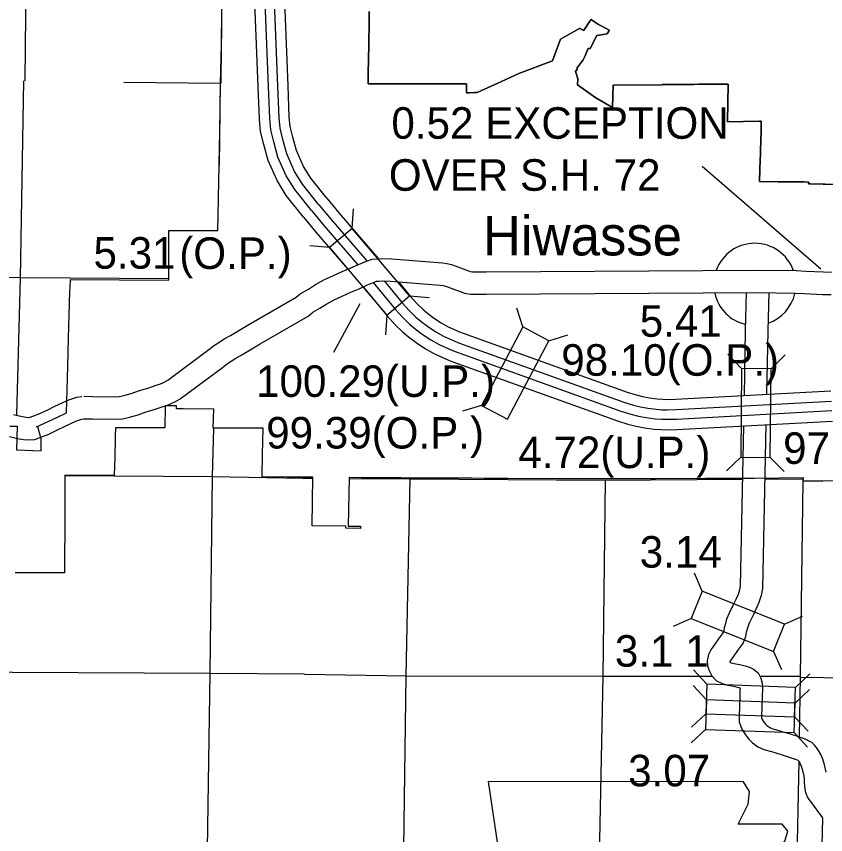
# Model space of a CAD drawing. Extents: x 77230 to 630905, y 790554 to 1662844.
# Drawn here: x 176223 to 197917, y 1598656 to 1620575 of the extents above; entities that cross this region are included whole.
import ezdxf

# ---------------------------------------------------------------- set-up
doc = ezdxf.new("R2010")
doc.units = 0
for name, color, linetype in [('Level 12', 7, 'Continuous'), ('Level 15', 7, 'Continuous'), ('Level 16', 7, 'Continuous'), ('Level 19', 7, 'Continuous'), ('Level 22', 7, 'Continuous'), ('Level 24', 7, 'Continuous'), ('Level 26', 7, 'Continuous'), ('Level 27', 7, 'Continuous'), ('Level 29', 7, 'Continuous'), ('Level 31', 7, 'Continuous'), ('Level 32', 7, 'Continuous')]:
    doc.layers.add(name, color=color, linetype=linetype)

msp = doc.modelspace()

# ---------------------------------------------------------------- linework, layer by layer
at = {"layer": 'Level 12'}
for points in [[(176051, 1609595), (176241, 1609593), (176225, 1608965), (176884, 1608940), (176891, 1609260), (176802, 1609576), (176767, 1609577), (177307, 1609829), (177570, 1609952), (177586, 1610561), (177595, 1610905), (177602, 1611196), (177622, 1611963), (177630, 1612245), (177630, 1612263), (177661, 1613207), (177664, 1613308), (177671, 1613525), (178990, 1613514), (180307, 1613505), (180311, 1614841), (181620, 1614836), (181629, 1615240), (181649, 1616163), (181678, 1617493), (181697, 1618767), (181731, 1620161), (181735, 1621439)], [(191270, 1618905), (191211, 1619095), (191257, 1619158), (191252, 1619195), (191417, 1619408), (191451, 1619486), (191549, 1619713), (191568, 1619715), (191568, 1619715), (191601, 1619718), (191780, 1620065), (192060, 1620110), (192112, 1620200), (192114, 1620203), (191938, 1620300), (191868, 1620338), (191828, 1620361), (191775, 1620394), (191719, 1620431), (191671, 1620466), (191637, 1620491), (191636, 1620492), (191539, 1620362), (191494, 1620296), (191459, 1620238), (191437, 1620199), (191348, 1620244), (191336, 1620249), (191321, 1620250), (191308, 1620248), (191298, 1620243), (190889, 1620004), (190828, 1619971), (190810, 1619961), (190598, 1619380), (189692, 1619047), (189110, 1618780), (189051, 1618753), (188578, 1618536), (188514, 1618534), (188369, 1618528), (188368, 1618528), (188333, 1618527), (188287, 1618525), (188289, 1618767), (187688, 1618769), (187674, 1618769), (187500, 1618769), (187254, 1618769), (187240, 1618769), (187013, 1618769), (186976, 1618769), (186974, 1618769), (186314, 1618768), (185655, 1618770), (185654, 1618924), (185656, 1619039), (185663, 1619440), (185668, 1619787), (185679, 1620461), (185684, 1620707)], [(185684, 1620707), (185679, 1620461), (185668, 1619787), (185663, 1619440), (185656, 1619039), (185654, 1618924)], [(185654, 1618924), (185655, 1618770), (186314, 1618768), (186974, 1618769), (186976, 1618769), (187013, 1618769), (187240, 1618769), (187254, 1618769), (187500, 1618769), (187674, 1618769), (187688, 1618769), (188289, 1618767), (188287, 1618525), (188333, 1618527), (188368, 1618528), (188369, 1618528), (188514, 1618534), (188578, 1618536), (189051, 1618753), (189110, 1618780), (189692, 1619047), (190598, 1619380), (190810, 1619961), (190828, 1619971), (190889, 1620004), (191298, 1620243), (191308, 1620248), (191321, 1620250), (191336, 1620249), (191348, 1620244), (191437, 1620199), (191459, 1620238), (191494, 1620296), (191539, 1620362), (191636, 1620492), (191637, 1620491), (191671, 1620466), (191719, 1620431), (191775, 1620394), (191828, 1620361), (191868, 1620338), (191938, 1620300), (192114, 1620203), (192112, 1620200), (192060, 1620110), (191780, 1620065), (191601, 1619718), (191568, 1619715), (191568, 1619715), (191549, 1619713), (191451, 1619486), (191417, 1619408), (191252, 1619195), (191257, 1619158), (191211, 1619095), (191270, 1618905), (191268, 1618740), (191754, 1618395), (192207, 1618130), (192220, 1618734), (193523, 1618745), (193536, 1618746), (193581, 1618746), (193709, 1618747), (193710, 1618747), (193715, 1618747), (193730, 1618747), (193759, 1618747), (193832, 1618748), (194381, 1618753), (194511, 1618754), (194851, 1618757), (194897, 1618757), (194904, 1618757), (194917, 1618757), (195307, 1618759), (195288, 1617747), (196141, 1617770), (196185, 1617771), (196187, 1617485), (196185, 1617438), (196185, 1617434), (196181, 1617284), (196180, 1617260), (196179, 1617227), (196179, 1617217), (196179, 1617200), (196177, 1617157), (196176, 1617124), (196175, 1617096), (196167, 1616839), (196165, 1616783), (196163, 1616719), (196156, 1616478), (196146, 1616147), (196157, 1616147), (196157, 1616147), (196643, 1616143), (197001, 1616140), (197028, 1616140)], [(198293, 1616072), (197906, 1616081), (197876, 1616082), (197848, 1616082), (197505, 1616091), (197461, 1616092), (197462, 1616126), (197462, 1616137), (197448, 1616137), (197331, 1616138), (197204, 1616139), (197028, 1616140), (197001, 1616140), (196643, 1616143), (196157, 1616147), (196157, 1616147), (196146, 1616147), (196156, 1616478), (196163, 1616719), (196165, 1616783), (196167, 1616839), (196175, 1617096), (196176, 1617124), (196177, 1617157), (196179, 1617200), (196179, 1617217), (196179, 1617227), (196180, 1617260), (196181, 1617284), (196185, 1617434), (196185, 1617438), (196187, 1617485), (196185, 1617771), (196141, 1617770), (195288, 1617747), (195307, 1618759), (194917, 1618757), (194904, 1618757), (194897, 1618757), (194851, 1618757), (194511, 1618754), (194381, 1618753), (193832, 1618748), (193759, 1618747), (193730, 1618747), (193715, 1618747), (193710, 1618747), (193709, 1618747), (193581, 1618746), (193536, 1618746), (193523, 1618745), (192220, 1618734), (192207, 1618130), (191754, 1618395), (191268, 1618740), (191270, 1618905)], [(197028, 1616140), (197204, 1616139), (197331, 1616138), (197448, 1616137), (197462, 1616137), (197462, 1616126), (197461, 1616092), (197505, 1616091), (197848, 1616082), (197876, 1616082), (197906, 1616081), (198293, 1616072)], [(199008, 1608116), (197318, 1608135), (197319, 1608209), (196004, 1608198), (194680, 1608196), (193352, 1608188), (192025, 1608184), (191695, 1608186), (190728, 1608190), (189403, 1608196), (189077, 1608197), (188750, 1608199), (188423, 1608200), (188092, 1608201), (187773, 1608202), (187441, 1608204), (187135, 1608205), (187116, 1608205), (186920, 1608206), (186780, 1608207), (186616, 1608208), (186540, 1608209), (186404, 1608210), (186338, 1608210), (186298, 1608210), (185942, 1608213), (185870, 1608214), (185835, 1608214), (185769, 1608214), (185733, 1608215), (185729, 1608215), (185475, 1608217), (185142, 1608219), (185119, 1606920), (185451, 1606916), (185450, 1606855), (185053, 1606861), (185054, 1606921), (184155, 1606932), (184170, 1608227), (184140, 1608227), (183475, 1608232), (182811, 1608237), (182823, 1608868), (182829, 1609169), (182836, 1609545), (182235, 1609546), (181502, 1609547), (181513, 1610049), (180696, 1610066), (180516, 1610065), (180517, 1610144), (180216, 1610144), (180202, 1609549), (179590, 1609550), (178881, 1609551), (178879, 1609487), (178876, 1609370), (178868, 1609046), (178866, 1609001), (178860, 1608758), (178848, 1608291), (178847, 1608272), (178723, 1608273), (178656, 1608274), (177527, 1608284)], [(177527, 1608284), (177525, 1607775), (177525, 1607627), (177523, 1607220), (177522, 1606984), (177520, 1606700), (177517, 1606228), (177512, 1605665), (176189, 1605673)]]:
    msp.add_lwpolyline(points, dxfattribs=at)
at = {"layer": 'Level 15'}
for points in [[(179103, 1618815), (181690, 1618785), (181698, 1618785)], [(197216, 1601269), (197246, 1602891), (197316, 1608134), (197317, 1608209)], [(197076, 1592822), (197149, 1597589), (197204, 1600622)]]:
    msp.add_lwpolyline(points, dxfattribs=at)
at = {"layer": 'Level 16'}
for points in [[(176463, 1618850), (176490, 1621511)], [(181725, 1620751), (181706, 1618783)], [(176238, 1609904), (176335, 1613566), (176421, 1618851)], [(181690, 1618785), (181659, 1616582)], [(180307, 1613546), (176337, 1613572), (171018, 1613614), (165878, 1613680)], [(181508, 1609547), (181473, 1608252), (181411, 1602977), (181332, 1597688), (181285, 1592726)], [(177527, 1608274), (181469, 1608248), (183906, 1608201)], [(183906, 1608201), (184170, 1608200)], [(185141, 1608197), (186778, 1608191), (192007, 1608152)], [(186557, 1592753), (186603, 1597638), (186668, 1602911), (186780, 1608189), (186780, 1608207)], [(196279, 1608178), (197312, 1608184)], [(192007, 1608152), (191943, 1602895), (191838, 1597625), (191829, 1592779)], [(192007, 1608152), (195687, 1608174)], [(197312, 1608136), (197846, 1608128)], [(183945, 1602956), (181410, 1602975), (176124, 1603003), (170893, 1603062), (165773, 1603084)], [(183945, 1602956), (186670, 1602911), (191943, 1602899), (194877, 1602899)], [(196160, 1602899), (197248, 1602899)], [(197244, 1602871), (202871, 1602794), (208170, 1602710), (209003, 1602702)]]:
    msp.add_lwpolyline(points, dxfattribs=at)
at = {"layer": 'Level 19'}
for p, q in [((185221, 1614896), (185263, 1615423)), ((184618, 1614383), (184092, 1614425)), ((186761, 1613087), (187288, 1613045)), ((186158, 1612574), (186116, 1612047)), ((189799, 1612255), (189643, 1612760)), ((190499, 1611886), (191004, 1612042)), ((195664, 1611145), (195294, 1611522)), ((196456, 1611137), (196833, 1611507)), ((188690, 1610154), (188185, 1609998)), ((195640, 1608769), (195263, 1608400)), ((196432, 1608761), (196802, 1608384)), ((194608, 1605178), (194399, 1605663)), ((196815, 1604298), (197300, 1604507)), ((194315, 1604442), (193830, 1604234)), ((196522, 1603563), (196730, 1603077)), ((194736, 1602683), (194376, 1603069)), ((197111, 1602601), (197497, 1602962)), ((194722, 1602263), (194362, 1602649)), ((197096, 1602181), (197482, 1602541)), ((194709, 1601892), (194323, 1601532)), ((197084, 1601810), (197444, 1601424)), ((194695, 1601471), (194308, 1601111)), ((197069, 1601389), (197429, 1601003))]:
    msp.add_line(p, q, dxfattribs=at)
for points in [[(186761, 1613087), (185221, 1614896), (184618, 1614383), (186158, 1612574)], [(189799, 1612255), (188690, 1610154), (189390, 1609784), (190499, 1611886)], [(196432, 1608761), (196456, 1611137), (195664, 1611145), (195640, 1608769)], [(196815, 1604298), (194608, 1605178), (194315, 1604442), (196522, 1603563)], [(194709, 1601892), (197084, 1601810), (197111, 1602601), (194736, 1602683)], [(197096, 1602181), (194722, 1602263), (194695, 1601471), (197069, 1601389)]]:
    msp.add_lwpolyline(points, close=True, dxfattribs=at)
at = {"layer": 'Level 22'}
for points in [[(183691, 1613029), (183834, 1613144), (184052, 1613270), (184245, 1613389), (184483, 1613523), (184708, 1613628), (184954, 1613738), (185171, 1613826), (185396, 1613932), (185605, 1614017), (185758, 1614068), (185892, 1614080), (186040, 1614090), (186288, 1614079), (187648, 1613969), (187764, 1613953), (187889, 1613930), (187987, 1613893), (188340, 1613761), (188391, 1613741), (188448, 1613733), (188504, 1613733), (188624, 1613730), (188819, 1613731), (196085, 1613780), (197127, 1613764), (197383, 1613753), (197858, 1613728), (198077, 1613721)], [(184047, 1612546), (184174, 1612647), (184359, 1612755), (184549, 1612871), (184757, 1612988), (184958, 1613082), (185190, 1613186), (185411, 1613277), (185637, 1613382), (185814, 1613455), (185881, 1613477), (185939, 1613482), (186046, 1613489), (186250, 1613480), (187584, 1613372), (187668, 1613361), (187727, 1613350), (187778, 1613331), (188122, 1613203), (188235, 1613156), (188410, 1613133), (188498, 1613133), (188617, 1613130), (188822, 1613131), (196082, 1613180), (197110, 1613164), (197354, 1613154), (197833, 1613128), (198063, 1613121)], [(178032, 1610397), (178272, 1610395), (178880, 1610382), (178975, 1610390), (179103, 1610421), (179304, 1610476), (179524, 1610557), (179745, 1610616), (179973, 1610693), (180056, 1610719), (180128, 1610749), (180204, 1610786), (180281, 1610832), (181386, 1611651), (181533, 1611764), (181650, 1611840), (181798, 1611937), (181967, 1612026), (182453, 1612323), (183728, 1613055)], [(195790, 1613182), (195763, 1612156)], [(196390, 1613182), (196363, 1612141)], [(178028, 1609797), (178263, 1609795), (178899, 1609781), (179071, 1609796), (179254, 1609840), (179488, 1609905), (179705, 1609985), (179919, 1610042), (180157, 1610122), (180261, 1610154), (180376, 1610202), (180491, 1610259), (180613, 1610331), (181749, 1611173), (181880, 1611274), (181977, 1611337), (182103, 1611419), (182264, 1611505), (182759, 1611807), (184047, 1612546)], [(195763, 1612155), (195729, 1610420)], [(196363, 1612143), (196330, 1610453)], [(176151, 1609913), (176378, 1609854), (176483, 1609837), (176550, 1609832), (176597, 1609835), (176666, 1609861), (176855, 1609935), (177066, 1610037), (177258, 1610129), (177470, 1610229), (177631, 1610302), (177713, 1610332), (177846, 1610371), (177982, 1610393)], [(176039, 1609322), (176256, 1609265), (176415, 1609240), (176548, 1609231), (176721, 1609242), (176879, 1609299), (177096, 1609385), (177326, 1609496), (177516, 1609588), (177722, 1609684), (177859, 1609746), (177901, 1609762), (177979, 1609785), (178078, 1609801)], [(195713, 1609605), (195629, 1605314), (195610, 1605210), (195571, 1605092), (195514, 1604970), (195438, 1604810), (195328, 1604584)], [(196314, 1609638), (196228, 1605253), (196193, 1605061), (196130, 1604870), (196057, 1604714), (195979, 1604550), (195868, 1604321)], [(195328, 1604584), (195263, 1604424), (195229, 1604312), (195201, 1604192), (195190, 1604122), (195175, 1604086), (195141, 1604038), (195089, 1603960), (194840, 1603604), (194773, 1603478), (194741, 1603315), (194751, 1603174), (194795, 1603049), (194869, 1602913), (194994, 1602777), (195147, 1602701), (195292, 1602663), (195401, 1602644), (195485, 1602628), (195594, 1602601), (195623, 1602592), (195623, 1602589), (195621, 1602519), (195620, 1602450), (195614, 1602382), (195595, 1601823), (195599, 1601678), (195673, 1601479), (195747, 1601357), (195851, 1601222), (195959, 1601111), (196120, 1601003), (196260, 1600934), (196463, 1600880), (196585, 1600846), (196778, 1600788), (196913, 1600740), (197077, 1600684)], [(195877, 1604342), (195830, 1604225), (195809, 1604156), (195790, 1604076), (195771, 1603957), (195703, 1603793), (195634, 1603696), (195583, 1603621), (195353, 1603290), (195350, 1603285), (195360, 1603266), (195422, 1603249), (195509, 1603234), (195613, 1603214), (195756, 1603179), (195877, 1603141), (195984, 1603086), (196111, 1602986), (196181, 1602844), (196219, 1602713), (196223, 1602593), (196221, 1602507), (196219, 1602420), (196214, 1602348), (196195, 1601821), (196196, 1601794), (196216, 1601741), (196243, 1601696), (196304, 1601616), (196344, 1601575), (196421, 1601524), (196473, 1601498), (196622, 1601458), (196752, 1601422), (196964, 1601358), (197109, 1601307), (197270, 1601253)], [(197930, 1600327), (197882, 1600528), (197839, 1600673), (197788, 1600805), (197728, 1600909), (197672, 1600988), (197617, 1601049), (197546, 1601123), (197457, 1601171), (197387, 1601207), (197283, 1601248)], [(197814, 1598012), (197843, 1599097), (197831, 1599113), (197786, 1599179), (197518, 1599541), (197476, 1599598), (197432, 1599669), (197390, 1599778), (197368, 1599871), (197356, 1599958), (197350, 1600063), (197348, 1600153), (197340, 1600218), (197302, 1600373), (197271, 1600479), (197246, 1600544), (197221, 1600587), (197204, 1600612), (197179, 1600638), (197178, 1600640), (197140, 1600659), (197063, 1600689)]]:
    msp.add_lwpolyline(points, dxfattribs=at)
at = {"layer": 'Level 24'}
msp.add_lwpolyline([(188872, 1600077), (189214, 1597793), (189062, 1594329), (189367, 1594139), (189938, 1594139), (189938, 1592921), (194734, 1592921), (194962, 1593416), (194886, 1594215), (195000, 1595129), (195419, 1595852), (195685, 1596385), (196066, 1596956), (196294, 1597565), (196485, 1598060), (196827, 1598478), (196903, 1598745), (196751, 1598935), (195571, 1598935), (195838, 1599468), (195876, 1599811), (195718, 1600074)], close=True, dxfattribs=at)
at = {"layer": 'Level 26'}
for start, end in [(19.7706, 159.9223), (192.5455, 257.0069), (289.1572, 347.4534)]:
    msp.add_arc((196017, 1613396), 1100, start, end, dxfattribs=at)
at = {"layer": 'Level 29'}
for points in [[(183927, 1615188), (183459, 1615778), (183211, 1616174), (182974, 1616713), (182853, 1617142), (182772, 1617493), (182738, 1617817), (182708, 1618685), (182579, 1621853), (182495, 1624200), (182449, 1625062), (182472, 1625625), (182526, 1626497), (182724, 1628916), (182966, 1632050), (182966, 1632430), (182951, 1632869), (182892, 1633386), (182841, 1633759), (182740, 1634214), (182631, 1634561), (182424, 1635132), (182161, 1635747), (181163, 1638058)], [(184140, 1615366), (183686, 1615938), (183457, 1616304), (183236, 1616807), (183122, 1617211), (183046, 1617539), (183016, 1617836), (182985, 1618695), (182856, 1621864), (182773, 1624212), (182727, 1625063), (182750, 1625611), (182803, 1626478), (183000, 1628894), (183243, 1632040), (183243, 1632434), (183228, 1632889), (183168, 1633421), (183115, 1633808), (183008, 1634285), (182895, 1634649), (182682, 1635234), (182417, 1635857), (181464, 1638064)], [(184333, 1615526), (183891, 1616083), (183680, 1616422), (183473, 1616892), (183365, 1617274), (183294, 1617580), (183266, 1617853), (183236, 1618705), (183107, 1621873), (183023, 1624223), (182978, 1625065), (183001, 1625598), (183053, 1626460), (183251, 1628874), (183494, 1632030), (183494, 1632438), (183479, 1632908), (183417, 1633452), (183362, 1633852), (183251, 1634350), (183133, 1634730), (182916, 1635326), (182647, 1635956), (181735, 1638068)], [(184544, 1615702), (184116, 1616242), (183923, 1616550), (183732, 1616985), (183631, 1617342), (183565, 1617625), (183540, 1617872), (183510, 1618715), (183381, 1621884), (183297, 1624235), (183253, 1625067), (183275, 1625584), (183327, 1626440), (183524, 1628853), (183769, 1632019), (183769, 1632443), (183753, 1632928), (183689, 1633486), (183632, 1633900), (183516, 1634421), (183393, 1634818), (183171, 1635427), (182899, 1636064), (182031, 1638074)], [(184544, 1615702), (184867, 1615314), (185929, 1614083)], [(184333, 1615526), (184658, 1615137), (185619, 1614023)], [(184140, 1615366), (184466, 1614975), (185375, 1613922)], [(183927, 1615188), (184254, 1614795), (185111, 1613802)], [(185787, 1613443), (186376, 1612734), (186573, 1612515), (186763, 1612332), (186912, 1612205), (187098, 1612065), (187334, 1611910), (187558, 1611784), (187896, 1611631), (188017, 1611585), (192429, 1610003), (192693, 1609920), (192898, 1609869), (193109, 1609829), (193346, 1609798), (193524, 1609785), (193671, 1609781), (193917, 1609786), (198086, 1610015)], [(186080, 1613488), (186568, 1612900), (186756, 1612692), (186933, 1612521), (187071, 1612403), (187245, 1612272), (187466, 1612127), (187673, 1612011), (187994, 1611865), (188104, 1611824), (192510, 1610244), (192762, 1610164), (192952, 1610117), (193149, 1610080), (193372, 1610051), (193537, 1610039), (193672, 1610035), (193907, 1610040), (198073, 1610268)], [(186465, 1613462), (186780, 1613083), (186957, 1612886), (187121, 1612728), (187247, 1612621), (187406, 1612501), (187611, 1612366), (187799, 1612261), (188101, 1612123), (188201, 1612086), (192600, 1610509), (192838, 1610433), (193012, 1610390), (193193, 1610356), (193400, 1610329), (193551, 1610318), (193673, 1610314), (193896, 1610319), (198059, 1610547)], [(185520, 1613327), (186164, 1612552), (186372, 1612321), (186575, 1612125), (186737, 1611987), (186937, 1611836), (187189, 1611671), (187432, 1611535), (187789, 1611372), (187920, 1611323), (192339, 1609739), (192616, 1609651), (192838, 1609596), (193065, 1609552), (193318, 1609520), (193509, 1609506), (193670, 1609501), (193927, 1609507), (198099, 1609735)]]:
    msp.add_lwpolyline(points, dxfattribs=at)
at = {"layer": 'Level 31'}
for p, q in [((197786, 1613804), (194603, 1616549)), ((184729, 1611584), (185443, 1612881))]:
    msp.add_line(p, q, dxfattribs=at)

# ---------------------------------------------------------------- texts
at = {"layer": 'Level 27'}
msp.add_text('Hiwasse', height=1056, dxfattribs=at).set_placement((188730, 1614171))
at = {"layer": 'Level 31'}
for s, p in [('0.52 EXCEPTION', (186277, 1617296)), ('OVER S.H. 72', (186208, 1615903)), ('5.31', (178291, 1613816)), ('(O.P.)', (180591, 1613809)), ('5.41', (192934, 1611992)), ('98.10(O.P.)', (190829, 1610948)), ('100.29(U.P.)', (182649, 1610381)), ('99.39(O.P.)', (182920, 1608999)), ('4.72(U.P.)', (189679, 1608474)), ('97.36', (196777, 1608586))]:
    msp.add_text(s, height=844.8, dxfattribs=at).set_placement(p)
at = {"layer": 'Level 32'}
for s, p in [('3.14', (192933, 1605808)), ('3.1 1', (192268, 1603154)), ('3.07', (192624, 1599949))]:
    msp.add_text(s, height=844.8, dxfattribs=at).set_placement(p)

doc.saveas('drawing.dxf')
